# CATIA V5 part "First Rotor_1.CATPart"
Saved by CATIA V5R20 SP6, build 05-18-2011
Part number: First Rotor
Bounding box of the stored display mesh (mm): x -60 to 60, y 30 to 43.5, z 97.01 to 216.99
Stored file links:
  E:\#01 CATIA Lecture Materials\#06 DMU\#04 DMU Page01 KIN EX04\First Rotor_1.CATPart
  E:\#01 CATIA Lecture Materials\#06 DMU\#10 Kinematics Joints\#05 Gear Joint(Rotor)\Rotor Assambly.CATProduct
  E:\#01 CATIA Lecture Materials\#06 DMU\#10 Kinematics Joints\#002 Gear Joint(Rotor)\Main Body.CATPart
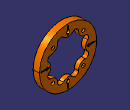
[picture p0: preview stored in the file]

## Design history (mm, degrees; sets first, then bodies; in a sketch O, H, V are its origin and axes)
Set1
  Line1 "First Rotor Axis": stored without definition
  Plane1: stored without definition
  Extract1: ExtractElem face of Solid1
  Boundary1 "Inner Boundary.1": Boundary edge of Extract1
Body1 (main body)
Body2 "First Rotor"
  Solid1: solid without history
